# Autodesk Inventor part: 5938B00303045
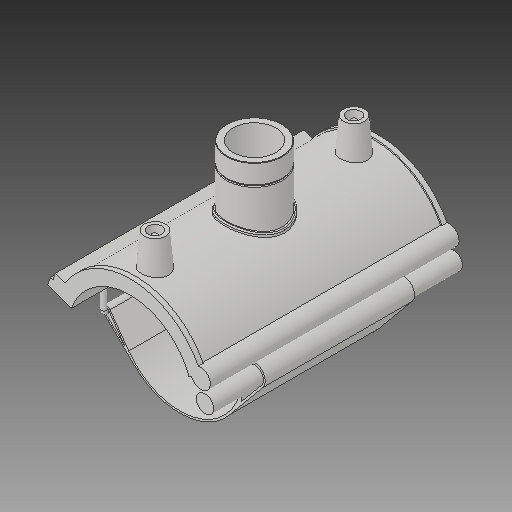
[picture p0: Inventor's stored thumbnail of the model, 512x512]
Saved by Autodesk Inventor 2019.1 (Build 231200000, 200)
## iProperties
Created: 2017-07
Part Number: 5938B00303045
Material: Generic
Description: PLASSON TRANSITION SADDLE 3''IPS x 1"NPT
Document SubType Name: Modeling
Designer: KIM
Density: 1 g/cm^3
Appearance: Default
Author: KIM
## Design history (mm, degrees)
derived "5938B.ipt"
feature "Solid1::5938B.ipt"
tag "TaggingFeature1"
body "Solid1"
other parameters: "d0" = 88.7, "d1" = 106.44, "d2" = 341.63, "d3" = 22.175, "d4" = 176.022, "d5" = 0, "d40" = 55.3488, "d41" = 42.4074, "d43" = 0, "d45" = 0, "d47" = 95.13, "d48" = 39.3783, "d50" = 0, "d78" = 75.22, "d79" = 15, "d80" = 70.4088, "d82" = 5 deg, "d84" = 4, "d85" = 14, "d86" = 0, "d87" = 3, "d88" = 0, "d96" = 108.5688, "d97" = 3.52044, "d98" = 0, "d102" = 0.90873, "d103" = 30.291, "d104" = 25.146, "d105" = 0, "d106" = 24.2328, "d108" = 0, "d109" = -13.97, "d111" = 0.5, "d112" = 0.5, "d113" = 0, "d114" = 0.5, "d117" = 0.30291, "d120" = 140 deg, "d121" = 24.228, "d122" = 20 deg, "d123" = 425.76, "d124" = 63.864, "d126" = 0, "d143" = 91.361, "d145" = 13.64615, "d149" = 1.3305, "d150" = 15.01077, "d153" = 176.022, "d154" = 0, "d156" = 53.22, "d157" = 160 deg, "d159" = 3.548, "d161" = 1.3305, "d162" = 105.6132, "d163" = 0, "d164" = 44.35, "d167" = 8.87, "d168" = 51.92195, "d170" = 1.3305, "d172" = 0, "d173" = 1, "d175" = 44.35, "d176" = 20 deg, "d177" = 6.209, "d178" = 17.74, "d180" = 0, "d183" = 7.096, "d184" = 4.9672, "d185" = 57.20715, "d186" = 57.20715, "d187" = 53.22, "d188" = 5.322, "d189" = 6.209, "d190" = 0, "d191" = 63.864, "d193" = 3.548, "d194" = 1.81835, "d195" = 90 deg, "d197" = 0, "d199" = 0, "d_" = 88.7, "B_" = 136.652, "H_" = 41.91, "L_" = 176.022, "d_t" = 6, "G_" = 30.291, "d148" = 1.3305, "d160" = 1.3305, "d169" = 1.3305, "d192" = 3.548
